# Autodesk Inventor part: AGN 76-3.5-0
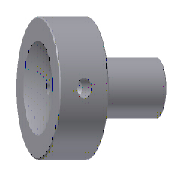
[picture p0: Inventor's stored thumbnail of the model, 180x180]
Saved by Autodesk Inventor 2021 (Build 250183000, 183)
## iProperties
IsCustomPart: 1
Created: 2019-01
Part Number: AGN 76-3.5-0
Material: DIN 1.2312
Description: Sprue Bushing
Document SubType Name: Modeling
Designer: LENOVO-CADCIM
Standard Revision: 1
Manufacturer: DME
Language: en-US
Size Designation: 76-3.5-0
Categories: <MemberInstance><Categories><Category DisplayName="Mold" InternalName="349578f2-f4d4-4954-8c09-8e99297a61c0" Mnemonic="MOLD"><Category DisplayName="Runners" Int
Density: 7.85 g/cm^3
Appearance: Default
Mass: 529.137 g
Surface Area: 115.001 cm^2
Volume: 67.406 cm^3
Author: LENOVO-CADCIM
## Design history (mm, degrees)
sketch "Sketch1"
  geometry: L1 (0, -27.2)-(0, 23.2) reference; L2 (1.75, 20)-(19, 20); L3 (19, 20)-(19, 0); L4 (19, 0)-(12, 0); L5 (9, -3)-(9, -76); L6 (9, -76)-(4.264, -76); L7 (4.264, -76)-(1.75, 20); A1 r 3 centre (12, -3) between (12, 0) and (9, -3); 2 further points
  constraints: 12 end point, 3 parallel, 2 perpendicular, 2 point on circle, 2 point on line, 2 tangent, 1 centre point
  dimensions: "d0" = 18 diameter of L5 L1 (= D); "d3" = 38 diameter of L3 L1 (= d1); "d6" = 1.5 deg angle of L7 L1 (= 0.5 x Taper); "d7" = 20 distance between parallel lines of L4 L2 (= K_); "d8" = 76 distance between parallel lines of L4 L6 (= L); "d9" = 3 radius of A1 (= R3); "d62" = 3.5 diameter of point (1.75, 20) L1 (= d_); "d63" = 0 distance from line of point (1.75, 20) L2 (computed from Rd)
revolve "Revolution1" sketch "Sketch1" stored, may be unused: angle "d10" = 90 deg
sketch "Sketch2"
  geometry: L1 (0, -32.79)-(0, 56.739) reference; L2 (4.264, -76)-(1.75, 20) reference; L3 (-19, 20)-(19, 20) reference; L4 (0, 50.901)-(0, 19.901); A1 r 15.5 centre (0, 35.401) between (0, 19.901) and (0, 50.901); 2 further points
  constraints: 3 point on circle, 3 point on line, 2 end point, 1 centre point, 1 midpoint
  dimensions: "d64" = 0 distance from line of point (1.75, 20) L3 (computed from Rd); "d67" = 15.5 radius of A1 (= Rk)
revolve "Revolution2" sketch "Sketch2" stored, may be unused: angle "d13" = 90 deg
workplane "Work Plane1"
sketch "Sketch3"
  geometry: 2 further points
  constraints: 1 vertical alignment
  dimensions: "d43" = 10 distance of point (0, -10) point (0, 0) (= 0.5 x K_)
hole "Hole1" sketch "Sketch3" at (0, 0) diameter "d15" = 4 (= pd1); stored, may be unused: countersink angle "d19" = 90 deg, drill point angle "d21" = 118 deg; dims "d16" = 6, "d17" = 4, "d18" = 2, "d20" = 6 (= pl1)
chamfer "Chamfer1" distance "d22" = 0.3; stored, may be unused: second distance "d23" = 2, angle "d24" = 45 deg
sketch "Sketch4"
  geometry: L1 (0, -30.4)-(0, 42.4) reference; L2 (0, 40)-(19.5, 40); L3 (19.5, 40)-(19.5, 0); L4 (9, -76)-(0, -76); L5 (0, -76)-(0, 40); L6 (9, -3)-(9, -76); L7 (12, 0)-(19.5, 0); L8 (12, 0)-(9, -3); 2 further points
  constraints: 14 end point, 4 point on line, 2 horizontal, 2 parallel, 1 perpendicular, 1 vertical
  dimensions: "d56" = 3 distance of L7.start point (9, 0) (= R3_CS); "d57" = 3 distance of L6.start point (9, 0) (= d56); "d58" = 39 diameter of L3 L1 (= d1_CS); "d59" = 40 distance between parallel lines of L7 L2 (= K_CS); "d60" = 18 diameter of L6 L1 (= D_CS); "d61" = 76 distance between parallel lines of L7 L4 (= L_CS)
feature "RevolutionSrf1" sketch "Sketch4" dims angle "d33" = 90 deg
body "Solid1"
body "Srf1"
other parameters: "L" = 76 [user parameter; used in 1 equation term], "d1" = 38 [user parameter; used in 1 equation term], "d_" = 3.5 [user parameter; used in 1 equation term], "D" = 18 [user parameter; used in 1 equation term], "K_" = 20 [user parameter; used in 2 equation terms], "R" = 0 [user parameter], "Taper" = 3 deg [user parameter; used in 1 equation term], "Rd" = 0 [user parameter; used in 2 equation terms], "R3" = 3 [user parameter; used in 1 equation term], "pd1" = 4 [user parameter; used in 1 equation term], "d1_CS" = 39 [user parameter; used in 1 equation term], "K_CS" = 40 [user parameter; used in 1 equation term], "d44" = 0, "d45" = 0, "d46" = 0, "L_CS" = 76 [user parameter; used in 1 equation term], "D_CS" = 18 [user parameter; used in 1 equation term], "pl1" = 6 [user parameter; used in 1 equation term], "R3_CS" = 3 [user parameter; used in 1 equation term], "Rk" = 15.5 [user parameter; used in 1 equation term]
